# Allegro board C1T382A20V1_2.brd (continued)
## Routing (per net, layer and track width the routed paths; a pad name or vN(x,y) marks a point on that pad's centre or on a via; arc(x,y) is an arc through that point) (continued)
CAN_5V: length 9.8
  TOP w0.5: R68.1 23.06,48.82 23.07,48.83 R31.1 ; v1(23.84,48.02) R31.1 ; R31.1 23.84,49.89 C49.1 22.71,49.92 Q1.3 ; R69.1 27.23,48.95 v1(27.23,49.68)
  BOTTOM w0.5: v1(23.84,48.02) 25.56,48.02 v1(27.23,49.68)
CAN_CANH: length 3
  TOP w0.2: U8.7 21.8,37.39 R29.1
CAN_CANH2: length 3.1
  TOP w0.2: U9.7 28.63,37.23 R36.1
CAN_CANL: length 3
  TOP w0.2: U8.6 20.54,37.38 R30.1
CAN_CANL2: length 3.1
  TOP w0.2: 26.87,36.8 27.37,37.3 27.37,39.68
CANH: length 32
  TOP w0.2: R29.2 22.28,32.76 22.51,32.53 J15.2 23.66,30.31 23.66,22.08 22.23,20.65 D8.2 22.23,18.23 J16.4 J16.3 20.14,6.1 J17.2
CANH2: length 31.7
  TOP w0.2: R36.2 29.07,32.69 29.27,32.49 J19.2 30.42,30.27 30.42,22.12 28.95,20.65 D9.2 28.95,18.12 J20.4 J20.3 30.94,5.73 J21.2
CANL: length 32
  TOP w0.2: R30.2 20.07,32.7 19.9,32.53 J18.2 18.75,30.31 18.75,22.06 20.19,20.61 D8.1 20.19,18.74 J16.6 J16.5 17.61,5.52 J17.1
CANL2: length 31.5
  TOP w0.2: J21.1 28.4,5.88 J20.5 J20.6 26.91,17.62 D9.1 26.91,20.65 25.48,22.08 25.48,30.21 J22.2 26.68,32.49 26.87,32.67 R37.2
DCDC_12V: length 43.8
  TOP w0.5: R53.1 56.02,16.58 C57.1 56.02,17.69 D14.C 58.16,19.82 61.52,19.82 62.21,19.14 C58.1 62.59,19.86 61.29,21.16 v1(59.29,21.16)
  POWER w0.5: S1.6 S1.1 50.25,30.2 v1(59.29,21.16)
DM2: length 53.2
  TOP w0.2: U3.8 36.5,37.55 37.19,36.86 39.79,36.86 v1(39.89,36.96) ; v1(65.03,11.16) 65.03,11 65.04,11 D2.2 65.03,10.45 64.71,10.12 64.71,10.11 64.66,10.07 J8.A7 64.66,6.65 64.42,6.42 63.89,6.42 63.66,6.65 J8.B7
  POWER w0.2: v1(65.03,11.16) 64.19,12 64.19,18.86 46.19,36.86 39.99,36.86 v1(39.89,36.96)
DMICCK: length 51.9
  TOP w0.2: v1(25.69,56.46) 25.69,56.46 23.48,58.67 20.93,58.67 U4.4 19.27,59.5 R9.2 18.33,59.5 12.43,53.6 12.43,49.01 8.96,45.54 J6.13 ; v1(46.38,52.91) 46.9,52.91 U5.4 48.36,53.53 48.38,53.52 R10.2
  BOTTOM w0.2: v1(25.69,56.46) 42.82,56.46 v1(46.38,52.91)
DMICDAT: length 51.8
  TOP w0.2: U5.5 46.7,54.36 36.71,54.36 33.55,57.53 v1(33.55,57.83) ; J6.15 8.96,43 12.96,47 12.96,53.56 17.34,57.94 20.01,57.94 U4.5 20.92,57.03 22.85,57.03 v1(23.59,57.76)
  BOTTOM w0.2: v1(33.55,57.83) 33.48,57.76 v1(23.59,57.76)
DP2: length 53.9
  TOP w0.2: J8.B6 65.16,8.96 65.25,9.05 v1(65.25,9.53) ; v1(39.29,36.26) 37.14,36.26 36,37.4 U3.7 ; v1(63.77,11.2) 63.77,11.03 63.78,11.01 D1.2 64.03,10.18 v1(64.03,9.52) 64.03,9.05 64.16,8.93 J8.A6
  POWER w0.2: v1(63.77,11.2) 63.77,18.71 46.02,36.46 40.29,36.46 40.09,36.26 v1(39.29,36.26)
  BOTTOM w0.2: v1(65.25,9.53) 64.78,9.53 64.78,9.52 v1(64.03,9.52)
EXT_3V3: length 23.7
  POWER w0.5: J9.7 8.78,70.67 8.78,69.01 5.63,65.86 v1(4.73,65.86)
  BOTTOM w0.5: v1(4.73,65.86) 4.73,58.72 7.75,55.7 J29.6 J29.8
EXT_12V: length 126.9
  TOP w0.5: D15.A 82.89,56.22 v1(82.91,56.21) ; 39.02,16.07 37.8,16.07 37.73,16.13 J20.2 ; J31.4 39.11,5.92 39.02,6.01 39.02,13.53
  POWER w0.5: J16.1 J16.2 24.39,17.86 31.75,17.86 J20.2 J20.1 ; 39.02,13.53 39.02,16.07 41.11,18.16 45.25,18.16 47.38,16.02 47.38,13.27 52.8,7.86 69.09,7.86 82.91,21.68 v1(82.91,56.21)
I3C_3V3: length 10.3
  TOP w0.5: R12.2 12.23,2.29 11.47,1.53 6.49,1.53 6.14,1.87 U6.8 6.14,2.72 C37.1 4.75,2.72 R63.2
I3C_ALERT: length 51.5
  TOP w0.2: J6.11 7.86,48.08 6.89,47.11 6.89,36.8 5.43,35.34 5.43,17.84 7.08,16.2 9.63,16.2 12.22,13.61 12.22,4.86 12.23,4.84 R12.1 11.75,3.9 11.64,4.02 U6.3
I3C_SCL: length 11.9
  TOP w0.2: J6.39 8.04,12.52 7.17,11.65 7.17,6.24 10.05,3.37 10.84,3.37
I3C_SDA: length 15.4
  TOP w0.2: 10.84,2.71 10.05,2.71 6.77,5.99 6.77,13.85 7.99,15.06 J6.37
LDO_3V3: length 133.5
  TOP w0.5: v1(50.55,53.29) 50.55,56.45 49.83,57.18 R61.1 ; R66.1 v1(28.02,50.61) ; R64.1 v1(17.84,40.4) ; R70.1 v1(53.38,42.27) ; R67.1 v1(24.67,40.4) ; R65.1 v1(40.91,43.16) ; R63.1 v1(3.84,4.32)
  POWER w0.5: v1(17.84,40.4) v1(24.67,40.4) 28.02,43.75 v1(28.02,50.61) 29.55,50.61 36.99,43.16 v1(40.91,43.16) 50.56,43.16 ; v1(50.55,53.29) 50.55,43.17 50.56,43.16 ; 50.56,43.16 52.49,43.16 v1(53.38,42.27) ; v1(10.29,48.96) 6.59,48.96 v1(5.49,47.86)
  BOTTOM w0.5: v1(17.84,40.4) 17.84,41.42 10.68,48.57 v1(10.29,48.96) ; v1(3.84,4.32) 3.84,10.21 5.49,11.86 v1(5.49,47.86) 5.49,47.96 2.83,50.62 2.1,50.62 2.1,53.16
LDO_5V: length 155.8
  TOP w0.5: v1(87.97,65.46) 87.97,65.47 C63.2 86.93,66.33 C64.1 86.49,66.33 C65.2 84.56,66.33 R57.1 83.62,66.31 83.58,66.28 U14.2 ; v1(6.73,32.84) v1(6.73,25.71)
  BOTTOM w0.5: v1(87.97,65.46) 84.54,65.46 77.63,58.55 77.63,17.7 68.64,8.71 59.69,8.71 57.61,10.79 57.61,14.08 52.8,18.89 8.86,18.89 6.73,21.02 v1(6.73,25.71) ; 8.4,32.84 v1(6.73,32.84)
LDO_VBUS: length 138.9
  TOP w0.5: D18.A 84.89,10.41 84.89,13.06 83.29,14.66 D17.A 83.23,14.65 v1(72.4,14.65) ; v1(20.37,52.99) 20.38,52.98 C48.1 21.53,52.26 Q1.2 21.54,52.93 R33.1
  POWER w0.5: v1(10.59,52.96) 8.09,50.46 5.49,50.46 2.99,47.96 v1(2.99,36.76) ; v1(11.89,26.46) v1(4.69,26.46)
  BOTTOM w0.5: v1(20.37,52.99) 20.34,52.96 v1(10.59,52.96) ; v1(4.69,26.46) 4.69,30.66 2.51,32.84 J29.23 2.1,35.38 2.49,35.38 2.99,35.88 v1(2.99,36.76) ; v1(11.89,26.46) 12.89,26.46 19.59,19.76 53.03,19.76 60.53,12.26 70.01,12.26 v1(72.4,14.65)
LED_B: length 21.5
  TOP w0.2: R17.1 56.35,49.23 58.39,47.2 v1(59.86,47.2) ; v1(68.27,46.23) 68.27,44.97 J7.25
  BOTTOM w0.2: v1(59.86,47.2) 60.83,46.23 v1(68.27,46.23)
LED_G: length 22.2
  TOP w0.2: v1(68.36,40.98) J7.29 ; R19.1 55.83,46.02 57.55,44.3 v1(58.2,44.3)
  BOTTOM w0.2: v1(58.2,44.3) 58.53,43.97 64.51,43.97 67.49,40.98 v1(68.36,40.98)
LED_R: length 20.4
  TOP w0.2: J7.23 67.81,47.42 66.92,48.31 66.92,48.37 v1(66.59,48.7) ; R16.1 56.35,50.85 58.23,48.97 v1(59.92,48.97)
  BOTTOM w0.2: v1(66.59,48.7) 66.32,48.97 v1(59.92,48.97)
LED_W: length 21.8
  TOP w0.2: v1(58.19,45.8) 58.18,45.8 56.35,47.64 R18.1 ; v1(68.41,43.45) 68.41,42.39 J7.27
  BOTTOM w0.2: v1(58.19,45.8) 65.21,45.8 67.57,43.45 v1(68.41,43.45)
LIN1_3V3: length 4.6
  TOP w0.4: R65.2 42.62,42.29 R51.2
  TOP w0.5: v1(45.18,40.94) 45.18,40.4 R39.1 ; R51.2 v1(43.06,42.28)
  BOTTOM w0.5: v1(43.06,42.28) 43.84,42.28 v1(45.18,40.94)
LIN1_12V: length 7.7
  TOP w0.4: D10.A 44.09,25.71 43.27,26.52 43.27,28.57 43.49,28.8 C52.2
  TOP w0.5: R71.2 44.79,28.8 C52.2 43.89,31.23
LIN2_3V3: length 4.5
  TOP w0.4: R70.2 51.16,42.27 51.12,42.3 50.09,42.3 R52.2
  TOP w0.5: R41.1 51.73,41.64 51.72,41.65 R70.2
LIN2_12V: length 7.6
  TOP w0.4: D11.A 50.64,25.6 49.84,26.41 49.84,28.39 50.43,28.99 C56.2 ; C56.2 51.35,28.99 R72.2 ; C56.2 50.45,29.06 50.46,29.07 50.46,30.53
  TOP w0.5: 50.46,31.23 50.46,30.53
LIN_12V: length 51.4
  TOP w0.5: v1(44.79,27.15) 44.79,27.8 R71.1 ; R72.1 v1(51.36,27.26)
  BOTTOM w0.5: v1(51.36,27.26) 51.35,27.26 50.85,26.76 45.18,26.76 v1(44.79,27.15) 44.79,29.16 39.79,34.16 16.49,34.16 10.19,40.46 J29.18
LIN_EN1: length 48
  TOP w0.2: J6.5 8.96,55.7 14.02,60.76 26.82,60.76 43.88,43.7 R43.1
LIN_EN2: length 27.4
  TOP w0.2: R44.1 v1(50.46,40.89) ; v1(68.36,56.36) J7.15
  BOTTOM w0.2: v1(68.36,56.36) 67.45,56.36 66.59,55.51 66.59,54.8 63.26,51.47 59.39,51.47 50.46,42.54 v1(50.46,40.89)
LIN_LIN1: length 32.5
  TOP w0.4: J31.2 44.09,9.72 J25.6 J25.5 40.64,19.52 40.64,24.25 J23.2 40.8,26.58 40.8,28.34 41.02,28.56 41.05,28.56 D12.2 41.46,28.98 42.31,28.98 C55.2 42.62,29.23 42.62,30.48
  TOP w0.5: 42.62,30.48 42.62,31.23
LIN_LIN2: length 32.2
  TOP w0.4: J31.1 52.46,6.43 J27.6 J27.5 47.12,21.37 47.12,24.11 J24.2 47.23,26.63 47.23,28.59 47.7,29.06 47.87,29.06 D13.2 48.45,29.06 48.45,29.06 48.79,29.06 C54.2 49.19,29.46 49.19,30.21
  TOP w0.5: 49.19,31.23 49.19,31.22 49.19,30.21
LIN_RXD1: length 51.9
  TOP w0.2: J6.3 8.97,58.24 11.89,61.16 26.99,61.16 44.52,43.63 44.52,40.04 R39.2 45.17,37.88 45.16,37.88 U10.1
LIN_RXD2: length 29.3
  TOP w0.2: v1(52.54,39.38) R41.2 51.73,39.38 U11.1 ; J7.17 68.36,53.89 v1(68.34,53.87)
  BOTTOM w0.2: v1(52.54,39.38) 52.54,44.05 59.56,51.07 63.42,51.07 66.22,53.86 67.78,53.86 67.78,53.87 v1(68.34,53.87)
LIN_TXD1: length 46.4
  TOP w0.2: R47.1 40.37,42.25 40.37,46.64 26.65,60.36 16.16,60.36 8.96,53.16 J6.7
LIN_TXD2: length 48.4
  TOP w0.2: R49.1 47.23,41.29 46.48,42.04 46.48,42.34 46.41,42.42 46.3,42.42 27.16,61.56 11.49,61.56 10.71,60.78 J6.1
TL_ANT: length 3
  TOP w0.2: 35.49,77.56 35.48,77.54 35.25,77.54 34.99,77.28 U1.43
  TOP w0.5: 35.49,77.56 35.52,77.56 C3.1 L1.1
TL_AVDD1P2: length 11.1
  TOP w0.2: C18.1 34.79,68.29 34.2,68.89 U1.26
  TOP w0.3: 37.89,65.46 39.69,65.46 39.99,65.16 AVDD1P2.1
  TOP w0.35: AVDD1P2.1 R138.2 ; 36.02,66.93 36.42,66.93 37.89,65.46
  TOP w0.4: C18.1 34.79,68.16 36.02,66.93
TL_CAN_RXD: length 29.9
  TOP w0.2: J6.31 8.96,22.68 12.63,26.35 12.63,38 19.27,44.64 U8.4 C43.2
TL_CAN_RXD2: length 33.7
  TOP w0.2: v1(13.67,27.76) 13.43,28.01 13.43,37.5 17.59,41.66 20.93,41.66 23.64,44.37 25.62,44.37 26.09,44.84 U9.4 26.09,47.28 26.08,47.3 C46.2 ; J6.27 v1(11.42,27.76)
  BOTTOM w0.2: v1(11.42,27.76) v1(13.67,27.76)
TL_CAN_STB: length 26.4
  TOP w0.2: R22.2 19.48,36.12 17.88,34.52 17.88,27.09 10.93,20.14 J6.33
TL_CAN_STB2: length 33.8
  TOP w0.2: J6.35 8.96,17.6 18.28,26.92 18.28,33.73 19.38,34.83 29.44,34.83 R24.2
TL_CAN_TXD: length 30.2
  TOP w0.2: v1(12.47,25.22) 13.03,25.78 13.03,37.8 17.29,42.05 20.52,42.05 23.07,44.61 U8.1 ; J6.29 v1(10.56,25.22)
  BOTTOM w0.2: v1(10.56,25.22) 11.96,25.22 11.96,25.22 v1(12.47,25.22)
TL_CAN_TXD2: length 33.3
  TOP w0.2: U9.1 29.91,42.73 28.42,41.25 24.77,41.25 24.61,41.09 24.15,41.09 23.99,41.25 17.78,41.25 13.98,37.45 v1(13.98,30.3) ; v1(11.49,30.3) J6.25
  BOTTOM w0.2: v1(11.49,30.3) 13.51,30.3 13.51,30.3 v1(13.98,30.3)
TL_KEY1: length 29.6
  TOP w0.2: SW4.1 SW4.2 75.28,87.41 74.51,88.18 68.05,88.18 67.28,87.41 SW3.2 SW3.1 67.28,77.31 68.36,76.23 J7.1
TL_KEY2: length 50.4
  TOP w0.2: SW5.2 v1(83.28,81.79) SW5.1 ; SW6.2 v1(59.28,81.79) SW6.1 ; v1(70.11,81.79) 70.11,80.16 70.14,80.12 70.14,74.05 68.91,72.82 J7.3
  BOTTOM w0.2: v1(83.28,81.79) v1(70.11,81.79) v1(59.28,81.79)
TL_KEY3: length 42.8
  TOP w0.2: SW5.3 v1(87.78,83.07) SW5.4 ; SW3.4 v1(71.78,83.07) SW3.3 71.78,73.15 68.91,70.28 J7.5
  BOTTOM w0.2: v1(71.78,83.07) v1(87.78,83.07)
TL_KEY4: length 63.6
  TOP w0.2: 78.61,88.58 64.95,88.58 63.78,87.41 SW6.4 SW6.3 63.78,71.77 67.81,67.74 J7.7 68.91,67.74 79.78,78.61 SW4.3 SW4.4 79.78,87.41 78.61,88.58
TL_MICBIAS: length 27.1
  TOP w0.2: v1(70.22,60.14) 68.38,60.14 J7.13
  TOP w0.5: R4.1 75.03,37.5 v1(75.03,37.5)
  BOTTOM w0.2: v1(70.22,60.14) 70.22,42.31 v1(75.03,37.5)
TL_PA0: length 44.9
  TOP w0.2: U1.16 30.2,69.47 29.39,68.66 28.09,68.66 26.39,66.96 v1(26.39,66.66) ; v1(60.41,65.2) J7.10
  POWER w0.2: v1(26.39,66.66) 28.29,66.66 33.39,61.56 56.77,61.56 v1(60.41,65.2)
TL_PA1: length 43.8
  TOP w0.2: v1(60.41,62.66) J7.12 ; U1.17 30.59,69.27 29.49,68.16 28.39,68.16 26.99,66.76 v1(26.99,66.06)
  POWER w0.2: v1(60.41,62.66) 58.91,61.16 33.09,61.16 28.19,66.06 v1(26.99,66.06)
TL_PA2: length 43.2
  TOP w0.2: v1(27.59,65.46) 27.59,66.56 28.69,67.66 29.69,67.66 30.99,68.96 U1.18 ; v1(60.41,60.12) J7.14
  POWER w0.2: v1(27.59,65.46) 27.69,65.46 32.39,60.76 59.77,60.76 v1(60.41,60.12)
TL_PA7: length 30.8
  TOP w0.2: U1.19 31.39,68.77 28.69,66.06 28.69,65.36 27.59,64.26 23.29,64.26 v1(22.89,64.66) ; R135.2 v1(6.3,68.08)
  BOTTOM w0.2: v1(6.3,68.08) 19.47,68.08 v1(22.89,64.66)
TL_PB0: length 60.8
  TOP w0.2: 18.22,82.29 17.97,82.54 ; 18.22,82.29 17.99,82.06 ; 18.22,82.29 18.45,82.06 ; 17.97,82.54 16.43,84.08 J10.1 ; 17.97,82.54 17.97,82.08 17.99,82.06 ; 17.99,82.06 17.84,81.91 v1(12.79,76.86) ; 17.99,82.06 18.45,82.06 ; 18.45,82.06 31.41,82.06 34.2,79.28 U1.45 ; v1(2.11,62.26) J6.2
  POWER w0.2: v1(2.11,62.26) 2.11,71.78 3.69,73.36 9.29,73.36 v1(12.79,76.86) ; J10.3 J10.1
TL_PB1: length 47.6
  TOP w0.2: U1.46 33.8,79.11 31.26,81.64 20.4,81.64 8.51,69.76 8.51,67.38 3.64,62.5 3.64,59.75 2.14,58.24 J6.4
TL_PB2: length 49.2
  TOP w0.2: U1.47 33.39,78.94 31.09,81.24 20.57,81.24 8.91,69.59 8.91,67.2 4.04,62.33 4.04,57.09 2.66,55.7 J6.6
TL_PB3: length 50.6
  TOP w0.2: J6.8 2.69,53.16 4.44,54.92 4.44,62.17 9.31,67.03 9.31,69.42 20.74,80.84 30.92,80.84 32.99,78.77 U1.48
TL_PB4: length 27.5
  TOP w0.2: U1.29 36.2,70.88 36.59,70.49 36.63,70.49 37.16,69.95 40.8,69.95 41.79,68.96 v1(47.49,68.96) ; J7.8 61.98,67.66 v1(60.39,67.66)
  POWER w0.2: v1(60.39,67.66) 59.09,68.96 v1(47.49,68.96)
TL_PB5: length 27.2
  TOP w0.2: J7.6 60.41,70.28 v1(60.39,70.26) ; v1(46.69,69.56) 41.79,69.56 40.99,70.36 37.32,70.36 36.4,71.28 U1.30
  POWER w0.2: v1(46.69,69.56) 59.69,69.56 v1(60.39,70.26)
TL_PB6: length 27.9
  TOP w0.2: U1.31 36.56,71.68 37.49,70.75 41.3,70.75 41.89,70.16 v1(47.49,70.16) ; v1(60.39,72.86) 62.02,72.86 J7.4
  POWER w0.2: v1(47.49,70.16) 57.69,70.16 v1(60.39,72.86)
TL_PB7: length 28.5
  TOP w0.2: v1(60.49,75.36) J7.2 ; U1.32 36.73,72.08 37.65,71.16 41.69,71.16 41.99,70.86 v1(46.69,70.86)
  POWER w0.2: v1(60.49,75.36) 55.99,70.86 v1(46.69,70.86)
TL_PC0: length 74.5
  TOP w0.2: 62.49,37.26 v1(63.79,37.26) ; 62.49,37.26 J7.32 ; 62.49,37.26 63.39,36.36 63.39,35.46 62.65,34.72 J7.34 ; U1.35 42.36,73.28 42.48,73.16 43.09,73.16 44.84,71.41 v1(47.44,71.41)
  POWER w0.2: v1(63.79,37.26) 64.26,37.73 64.26,73.89 61.89,76.26 58.37,76.26 53.52,71.41 v1(47.44,71.41)
TL_PC1: length 80.4
  TOP w0.2: J7.36 62.57,32.18 ; 62.57,32.18 v1(63.87,32.18) ; 62.57,32.18 63.39,31.36 63.39,30.36 62.67,29.64 J7.38 ; U1.36 42.53,73.68 42.66,73.56 43.39,73.56 44.59,72.36 v1(45.59,72.36)
  POWER w0.2: v1(63.87,32.18) 64.66,32.97 64.66,74.29 62.29,76.66 58.2,76.66 53.5,71.96 45.99,71.96 v1(45.59,72.36)
TL_PC2: length 85.2
  TOP w0.2: 47.02,74.69 47.02,74.59 46.49,74.06 v1(46.49,72.56) ; 47.02,74.69 R2.2 ; 47.02,74.69 46.22,74.69 45.49,73.96 42.82,73.96 42.7,74.08 U1.37 ; J7.40 v1(63.83,27.1)
  POWER w0.2: v1(46.49,72.56) 53.49,72.56 57.99,77.06 62.79,77.06 65.06,74.79 65.06,28.33 v1(63.83,27.1)
TL_PC3: length 86.4
  TOP w0.2: v1(51.29,77.46) 50,76.17 Y1.1 49.28,76.17 48.75,76.7 47.59,76.7 C6.2 46.81,76.19 44.99,74.36 42.99,74.36 42.87,74.48 U1.38 ; J7.42 v1(65.46,24.56)
  POWER w0.2: v1(65.46,24.56) 65.46,75.29 63.29,77.46 v1(51.29,77.46)
TL_PC4: length 64.6
  TOP w0.2: U1.39 43.04,74.88 43.16,74.76 44.59,74.76 v1(47.29,77.46) ; J7.24 63.54,47.42 63.55,47.42 v1(63.71,47.42)
  POWER w0.2: v1(66.01,47.42) 65.9,47.53 65.9,75.65 63.49,78.06 47.89,78.06 v1(47.29,77.46)
  BOTTOM w0.2: v1(66.01,47.42) 65.54,47.42 65.53,47.42 v1(63.71,47.42)
TL_PC5: length 50.8
  TOP w0.2: v1(56.94,42.57) 56.69,42.82 46.47,42.82 32.2,57.1 U1.21 ; J7.26 60.64,44.88 60.61,44.85 v1(59.97,44.85)
  BOTTOM w0.2: v1(59.97,44.85) 57.42,44.85 56.94,44.37 v1(56.94,42.57)
TL_PC6: length 48.4
  TOP w0.2: U1.22 32.59,57.26 46.64,43.22 60.63,43.22 61.51,42.34 J7.28
TL_PC7: length 53.4
  TOP w0.2: U1.23 32.99,57.43 46.8,43.62 63.01,43.62 63.69,42.94 63.69,40.88 62.61,39.8 J7.30
TL_PD0: length 54.2
  TOP w0.2: U1.49 32.59,78.6 30.75,80.44 20.9,80.44 9.71,69.26 9.71,66.86 4.84,62 4.84,52.08 v1(4.49,51.73) ; J6.9 7.93,50.62 7.19,51.36 v1(7.19,51.73)
  POWER w0.2: v1(7.19,51.73) v1(4.49,51.73)
TL_PD4: length 71.1
  TOP w0.2: v1(60.41,57.58) J7.16 ; U1.12 24.71,71.68 22.79,69.76 v1(22.79,69.56)
  POWER w0.2: v1(22.79,69.56) 22.79,68.36 30.79,60.36 57.63,60.36 v1(60.41,57.58)
  BOTTOM w0.2: v1(22.79,69.56) 10.29,69.56 8.97,70.88 6.03,70.88 J9.8
TL_PD5: length 74.2
  TOP w0.2: U1.11 24.21,72.08 22.56,70.43 v1(22.49,70.43) v1(20.79,70.43) ; v1(60.35,55.04) J7.18
  POWER w0.2: v1(60.35,55.04) 55.43,59.96 30.59,59.96 22.19,68.36 22.19,70.13 v1(22.49,70.43)
  BOTTOM w0.2: v1(20.79,70.43) 20.16,71.06 10.69,71.06 8.33,73.42 6.03,73.42 J9.6
TL_PD6: length 78.2
  TOP w0.2: J7.20 v1(60.3,52.5) ; v1(22.05,71.36) 22.05,71.42 23.11,72.48 U1.10
  POWER w0.2: v1(22.05,71.36) 22.05,70.92 21.79,70.66 21.79,68.06 30.29,59.56 53.24,59.56 v1(60.3,52.5)
  BOTTOM w0.2: J9.2 5.97,78.56 14.86,78.56 v1(22.05,71.36)
TL_PD7: length 79
  TOP w0.2: J7.22 61.94,50.08 60.61,50.08 59.8,50.89 59.8,50.9 v1(58.68,52.02) ; v1(21.35,71.06) 21.35,71.52 22.72,72.88 U1.9
  POWER w0.2: v1(58.68,52.02) 51.54,59.16 30.09,59.16 21.35,67.89 v1(21.35,71.06)
  BOTTOM w0.2: v1(21.35,71.06) 16.38,76.03 5.96,76.03 J9.4
TL_PE0: length 72.4
  TOP w0.2: U1.14 28.41,70.88 25.69,68.16 19.99,68.16 18.11,66.28 v1(18.11,65.12) ; v1(3.77,15.06) J6.38
  POWER w0.2: v1(18.11,65.12) 18.11,61.78 16.29,59.96 16.29,26 5.35,15.06 v1(3.77,15.06)
TL_PE2: length 74.1
  TOP w0.2: v1(18.66,65.72) 20.6,67.66 26.29,67.66 27.89,69.26 29.39,69.26 29.8,69.67 U1.15 ; v1(3.68,12.52) 3.54,12.52 3.54,12.52 J6.40
  POWER w0.2: v1(3.68,12.52) 16.69,25.53 16.69,59.66 18.66,61.63 v1(18.66,65.72)
TL_PF4: length 53.4
  TOP w0.2: J6.12 2.61,48.08 5.24,50.72 5.24,61.83 10.12,66.69 10.12,69.09 21.07,80.05 30.58,80.05 32.2,78.43 U1.50
TL_PF5: length 54.8
  TOP w0.2: J6.14 2.66,45.54 3.89,46.77 3.89,48.56 5.64,50.31 5.64,61.66 10.51,66.53 10.51,68.93 21.23,79.64 30.41,79.64 31.8,78.26 U1.51
TL_PF6: length 56.1
  TOP w0.2: J6.16 2.66,43 6.09,46.43 6.09,61.53 10.91,66.36 10.91,68.76 21.4,79.25 30.24,79.25 31.39,78.09 U1.52
TL_PF7: length 57.5
  TOP w0.2: U1.53 30.99,77.92 30.07,78.84 21.56,78.84 11.31,68.6 11.31,66.19 6.49,61.36 6.49,44.29 2.66,40.46 J6.18
TL_PG0: length 60.8
  TOP w0.2: v1(6.23,38.26) 5.9,37.93 2.11,37.93 J6.20 ; v1(11.71,65.72) 11.71,68.43 21.73,78.44 29.9,78.44 30.59,77.75 U1.54
  POWER w0.2: v1(11.71,65.72) 11.71,44.28 6.23,38.8 v1(6.23,38.26)
TL_PG1: length 61.2
  TOP w0.2: v1(6.26,37.45) 4.78,37.45 2.71,35.38 J6.22 ; v1(12.27,65.12) 12.27,68.33 12.46,68.51 12.46,68.6 21.9,78.05 29.7,78.05 30.2,77.55 U1.55
  POWER w0.2: v1(6.26,37.45) 6.78,37.97 6.78,38.45 12.29,43.96 12.29,65.1 v1(12.27,65.12)
TL_PG2: length 51.8
  TOP w0.2: J6.17 9.89,40.46 v1(10.79,41.36) ; v1(12.86,65.72) 12.86,68.43 21.96,77.54 29.54,77.54 29.8,77.28 U1.56
  POWER w0.2: v1(10.79,41.36) 12.69,43.26 12.69,62.46 12.86,62.62 v1(12.86,65.72)
TL_PG7: length 56.7
  TOP w0.2: v1(13.41,65.12) 13.41,68.42 21.08,76.08 U1.1 ; v1(11.69,35.46) 9.07,32.84 J6.23
  POWER w0.2: v1(13.41,65.12) 13.41,62.45 13.09,62.13 13.09,36.86 v1(11.69,35.46)
TL_PH0: length 64.4
  TOP w0.2: v1(14.04,65.75) 14.04,68.47 21.25,75.68 U1.2 ; v1(4.09,32.84) J6.24
  POWER w0.2: v1(4.09,32.84) 4.67,32.26 10.87,32.26 13.49,34.88 13.49,61.96 14.04,62.5 v1(14.04,65.75)
TL_PH2: length 64.8
  TOP w0.2: v1(3.89,30.33) 3.92,30.33 3.92,30.3 J6.26 ; v1(14.62,65.12) 14.62,68.48 21.42,75.28 U1.3
  POWER w0.2: v1(3.89,30.33) 9.51,30.33 13.89,34.71 13.89,61.66 14.62,62.39 v1(14.62,65.12)
TL_PH3: length 66
  TOP w0.2: J6.28 v1(3.93,27.76) ; U1.4 21.61,74.88 15.2,68.47 v1(15.2,65.75)
  POWER w0.2: v1(15.2,65.75) 15.2,62.33 14.29,61.42 14.29,33.88 8.17,27.76 v1(3.93,27.76)
TL_PH4: length 72
  TOP w0.2: v1(3.76,25.22) 3.74,25.22 3.74,25.22 J6.30 ; v1(15.77,65.12) 15.77,68.44 21.81,74.48 U1.5
  POWER w0.2: v1(3.76,25.22) 4.92,24.06 12.09,24.06 14.69,26.66 14.69,61.16 15.77,62.25 v1(15.77,65.12)
TL_PH5: length 71.9
  TOP w0.2: J6.32 3.74,22.68 3.74,22.68 v1(3.76,22.68) ; U1.6 22.01,74.08 16.37,68.44 v1(16.37,65.74)
  POWER w0.2: v1(16.37,65.74) 16.37,62.14 15.09,60.86 15.09,26.5 11.27,22.68 v1(3.76,22.68)
TL_PH6: length 72.8
  TOP w0.2: v1(16.98,65.12) 16.98,68.44 22.21,73.68 U1.7 ; v1(3.73,20.14) J6.34
  POWER w0.2: v1(16.98,65.12) 16.98,62 15.49,60.51 15.49,26.33 9.3,20.14 v1(3.73,20.14)
TL_PH7: length 73.6
  TOP w0.2: v1(17.55,65.77) 17.55,68.42 22.41,73.28 U1.8 ; J6.36 3.59,17.6 3.59,17.6 v1(3.68,17.6)
  POWER w0.2: v1(3.68,17.6) 7.32,17.6 15.89,26.16 15.89,60.26 17.55,61.92 v1(17.55,65.77)
TL_RF: length 4.6
  TOP w0.5: J1.1 D16.2 C5.1 L2.2
TL_RST: length 27.7
  TOP w0.2: SW1.2 SW1.1 50.56,78.96 50.55,78.95 C8.1 49.21,78.95 46.96,81.2 40.01,81.2 38.84,80.04 38.84,78.17 36.76,76.08 U1.42
TL_SDMN0: length 13.4
  TOP w0.2: L6.1 71.07,43.81 69.83,45.05 69.83,48.18 69.19,48.82 67.27,48.82 67.05,49.04 67.05,49.04 66.89,49.19 66.89,51.58 67.81,52.5 J7.19
TL_SDMN1: length 12.6
  TOP w0.2: J7.39 67.81,27.1 66.38,25.67 66.38,23.25 71.11,18.51 L4.1
TL_SDMP0: length 4.8
  TOP w0.2: J7.21 68.91,49.96 70.01,51.06 70.01,51.64 70.16,51.78 71.97,51.78 L7.1
TL_SDMP1: length 4.5
  TOP w0.2: J7.41 68.91,24.56 70.1,25.75 70.36,25.75 71.09,26.48 L5.1
TL_VBAT: length 52.6
  TOP w0.2: U1.28 34.99,69.68 35.24,69.44
  TOP w0.35: 37.13,69.09 36.79,69.44 35.24,69.44
  TOP w0.4: v1(37.49,69.06) 37.16,69.06 37.13,69.09
  TOP w0.5: v1(37.49,69.06) 38.41,69.06 C15.1
  POWER w0.5: v1(2.1,59.56) 15.2,72.66 22.99,72.66 24.09,71.56 24.09,69.56 24.59,69.06 v1(37.49,69.06)
  BOTTOM w0.5: 2.1,55.7 v1(2.1,59.56) 2.1,60.78
TL_VDD1P2: length 5.7
  TOP w0.5: VDD1P2.1 R139.1 R138.1 C72.1 37.19,64.76 35.86,63.43 L3.2
TL_VDD3DCDC: length 10.8
  TOP w0.2: U1.24 33.39,68.27 33.47,68.2
  TOP w0.35: 33.69,64.66 33.71,64.66 34.29,65.24 34.29,66.26 33.59,66.96 C17.1 33.47,67.03 33.47,68.2
  TOP w0.4: VDD3DCDC.1 34.29,60.46 34.29,64.06 33.69,64.66 R141.2
TL_VDDCORE: length 4.7
  TOP w0.2: U1.20 31.8,68.36 31.59,68.16
  TOP w0.4: C16.1 31.59,67 31.59,68.16
  TOP w0.5: VDDCORE.1 30.79,66.96 C16.1
TL_VDDIOPE: length 6.1
  TOP w0.2: U1.13 28.11,71.28 27.83,71
  TOP w0.35: C13.1 27.83,71
  TOP w0.4: C13.1 26.59,70.97 R140.2 26.59,70.04 25.81,69.26 VDDIOPE.1
TL_VDDO3: length 71.4
  TOP w0.2: 37.18,72.37 37.07,72.48 U1.33 ; VDDO3.1 42.79,71.56 38.49,71.56 v1(38.31,71.74)
  TOP w0.4: R141.1 v1(33.59,62.96) ; R140.1 v1(24.89,70.06) ; R20.2 v1(22.82,87.61) ; 37.18,72.37 37.34,72.2 C12.1 v1(38.31,71.74)
  POWER w0.4: 26.98,72.16 26.29,71.46 v1(24.89,70.06) ; 26.98,72.16 22.31,76.83 22.31,79.02 ; 26.98,72.16 27.98,71.16 37.73,71.16 v1(38.31,71.74) 38.99,71.06 38.99,66.36 35.59,62.96 v1(33.59,62.96) ; 22.31,79.02 21.78,79.55 21.78,79.57 ; 22.31,79.02 22.31,79.53 ; 22.31,79.53 22.31,80.1 ; 22.31,79.53 22.27,79.57 21.78,79.57 ; 22.31,80.1 22.31,85.88 22.3,85.89 22.3,86.43 22.31,86.44 22.31,87.09 v1(22.82,87.61) ; 22.31,80.1 22.26,80.05 22.09,80.05 21.79,79.75 21.79,79.58 21.78,79.57 ; 21.78,79.57 7.5,79.57 J9.1
TL_VLINE: length 35.8
  TOP w0.2: U1.44 34.59,77.67 34.7,77.77
  TOP w0.4: 34.7,77.77 34.7,79.91 C1.1
  TOP w0.5: VLINE.1 31.19,83.13 v1(32.23,82.09) 32.79,81.53 C2.1 33.07,81.44 33.82,80.69 C1.1 ; R139.2 v1(39.29,62.96)
  BOTTOM w0.4: v1(32.23,82.09) 29.19,79.05 29.19,68.76 34.99,62.96 v1(39.29,62.96)
TL_XC1: length 8.9
  TOP w0.2: 43.43,76.58 43.43,76.62 42.52,77.55 40.74,77.55 40.6,77.4 C11.1 39.22,77.4 37.1,75.28 U1.40
TL_XC2: length 7
  TOP w0.2: Y2.1 40.7,78.31 C9.2 39.55,78.31 36.92,75.68 U1.41
UART_5V: length 15.5
  TOP w0.35: v1(38.66,39.22) R62.1 C75.1 37.28,41.24 U3.9 ; C77.1 31.71,42.5 v1(32.05,42.17) 32.37,41.84 34.33,41.84
  BOTTOM w0.35: v1(32.05,42.17) 34.37,39.85 38.02,39.85 v1(38.66,39.22)
UART_RX: length 48.4
  TOP w0.2: J6.21 8.96,35.38 10.67,37.09 10.67,39.07 15.4,43.8 15.4,49.43 19.96,53.99 28.06,53.99 30.78,51.27 30.78,40.98 R136.2
UART_TX: length 45.9
  TOP w0.2: J6.19 8.96,37.92 15,43.96 15,49.6 19.8,54.39 27.89,54.39 27.89,54.39 28.23,54.39 28.23,54.39 28.29,54.39 31.19,51.49 31.19,41.54 R137.2
USB_5V: length 90
  TOP w0.5: R62.2 v1(38.19,37.71) ; v1(67.29,14.06) 64.09,14.06 60.43,10.4 R15.1
  POWER w0.5: v1(37.89,33.36) 37.89,37.41 v1(38.19,37.71) 38.73,38.26 49.99,38.26 67.29,20.96 v1(67.29,14.06)
  BOTTOM w0.5: J29.20 J29.22 10.27,35.38 12.31,33.34 37.87,33.34 v1(37.89,33.36)
USB_VBUSU: length 10.6
  TOP w0.5: J8.B4A9 66.81,6.59 65.88,5.66 62.94,5.66 62.01,6.59 J8.A4B9 62.01,8.4 D3.2 61.33,8.62 C71.1 60.29,8.62 R15.2
N20253886: length 2.5
  TOP w0.2: U2.4 74.44,39.66 74.48,39.66 R4.2 75.93,39.12 C22.1
N20253935: length 1.2
  TOP w0.2: C21.1 72.17,39.8 72.19,39.78 U2.1
N20253959: length 3.8
  TOP w0.2: C26.1 78.48,39.52 80.33,39.52
N20337202: length 4.4
  TOP w0.2: C23.1 74.41,22.13 R3.1 ; C23.1 C19.2 ; C23.1 73.84,21.56 L4.2
N20337204: length 10.1
  TOP w0.2: J2.2 82.43,18.1 78.41,22.12 C20.2 77.16,22.13 R3.2
N20337251: length 4.3
  TOP w0.2: C23.2 75.22,23.07 R5.1 ; C23.2 74,23.43 L5.2 ; C23.2 C24.1
N20337259: length 6.6
  TOP w0.2: 80.33,26.8 80.33,25.08 78.29,23.04 C25.1 R5.2
N20337346: length 4.4
  TOP w0.2: C31.1 73.78,46.86 L6.2 ; C31.1 74.34,47.42 R7.1 ; C31.1 74.32,46.92 74.32,46.91 C27.2
N20337363: length 10
  TOP w0.2: J4.2 81.32,43.77 77.66,47.42 C28.2 77.15,47.42 R7.2
N20337410: length 4.3
  TOP w0.2: C31.2 74.37,48.34 R8.1 ; C31.2 74.01,48.7 L7.2 ; C31.2 74.32,49.29 C32.1
N20337418: length 6.8
  TOP w0.2: R8.2 76.26,48.35 C33.1 77.97,48.35 80.36,50.75 J4.3
N20392329: length 1.3
  TOP w0.2: R16.2 47.93,50.85 47.93,50.84 D4.A
N20392898: length 1.3
  TOP w0.2: R17.2 47.93,49.23 47.93,49.23 D5.A
N20393445: length 1.3
  TOP w0.2: R18.2 47.95,47.64 47.95,47.63 D6.A
N20393873: length 1.3
  TOP w0.2: D7.A 47.97,46.02 47.97,46.02 R19.2
N20432643: length 1.8
  TOP w0.5: L2.1 C4.1 L1.2
N20432803: length 2.6
  TOP w0.2: R2.1 47.98,73.69 C7.2 49.64,73.72 Y1.2
N20433121: length 5.2
  TOP w0.2: C10.1 40.67,72.88 U1.34
N20433225: length 5.3
  TOP w0.2: 34.02,68.32 33.8,68.54 U1.25
  TOP w0.35: L3.1 35.67,66.34 34.02,68 34.02,68.32
N20446669: length 4.6
  TOP w0.5: D14.A 59.69,18.27 59.08,17.67 U13.1 59.49,15.95 L8.1
N20446778: length 8.5
  TOP w0.5: D17.C 83.24,10.76 81.2,10.76 C59.2 81.15,10.77 C60.1 U12.1 77.87,10.77 77.29,11.35 77.29,12.16 77.8,12.67 U12.3
N20446804: length 3.4
  TOP w0.5: U13.3 57.18,16.11 56.66,15.59 C57.2 56.02,15.58 R53.2 55.11,14.69 R55.1
N20446808: length 2.1
  TOP w0.5: R56.1 57.28,12.84 R54.2 57.18,12.95 U13.4
N20447279: length 4
  TOP w0.5: R57.2 84.55,68.2 R59.1 ; R57.2 85.45,67.31 C65.1 ; R57.2 83.93,67.31 83.69,67.55 U14.3
N20447283: length 3.7
  TOP w0.5: R60.1 74.75,68.73 R58.2 75.38,68.74 76.56,67.55 U14.6
N20449113: length 1.3
  TOP w0.2: R13.2 63.16,8.61 J8.A5
N20449208: length 1.3
  TOP w0.2: J8.B5 66.16,8.62 R14.2
N20451817: length 2.6
  TOP w0.2: R28.1 22.73,27.13 22.51,27.35 J15.1
N20451819: length 3.6
  TOP w0.2: R28.2 21.78,24.41 C47.1 20.63,24.42 R32.2
N20451956: length 2.6
  TOP w0.2: R32.1 19.63,27.14 19.9,27.41 J18.1
N20451988: length 2.6
  TOP w0.2: J19.1 29.27,27.36 29.55,27.08 R35.1
N20451990: length 3.7
  TOP w0.2: R38.2 27.37,24.36 C50.1 28.51,24.36 R35.2
N20452190: length 2.7
  TOP w0.2: R38.1 26.35,27.47 26.68,27.81 J22.1
N20458083: length 2.9
  TOP w0.2: U8.8 23.07,37.88 R22.1
N20458950: length 5.3
  TOP w0.5: R33.2 23.57,52.98 Q1.1 23.57,51.28 23.93,50.92 25.25,50.92 25.88,50.28 Q2.3
N20458968: length 2
  TOP w0.2: Q2.1 27.54,52.24 27.55,52.24 R66.2 28.02,52.25 R34.1
N20459724: length 2.6
  TOP w0.4: R40.2 45.71,29.23 45.16,29.77 45.16,30.48
  TOP w0.5: 45.16,30.48 45.16,31.23
N20459777: length 2.7
  TOP w0.2: U10.3 42.62,37.88 42.64,37.89 R45.2
N20459821: length 2.8
  TOP w0.2: R46.2 49.18,38.11 49.19,38.11 U11.3
N20459876: length 3.6
  TOP w0.2: R47.2 41.35,39.38 C51.2 41.37,37.64 41.35,37.62 U10.4
N20459892: length 1.3
  TOP w0.4: R48.2 44.53,22.21 D10.C
N20459907: length 3.7
  TOP w0.2: R49.2 47.91,39.4 C53.2 U11.4
N20481050: length 8.3
  TOP w0.5: D18.C 83.2,5 81.11,5 81.09,5.01 C70.1 79.83,5.02 U15.1 77.89,5.02 77.41,5.49 77.41,6.44 77.89,6.92 78.45,6.92
N20505812: length 8.9
  TOP w0.2: C73.1 81.69,33.86 J3.2
N20509362: length 5.6
  TOP w0.2: U3.12 37.38,42.84 37.67,43.14 37.67,46.76 37.67,46.76 TP4.1
N20509364: length 4.7
  TOP w0.2: TP5.1 38.62,43.25 37.72,42.34 U3.11
N20509368: length 1.8
  TOP w0.2: U3.10 38.24,41.84 38.25,41.85 TP6.1
N20509433: length 2.6
  TOP w0.2: U3.13 36.5,44.36 36.49,44.37 36.49,46.09 TP8.1
N20509448: length 4.7
  TOP w0.2: TP7.1 35.55,44.53 36,44.09 U3.14
N20509463: length 3.1
  TOP w0.2: U3.15 35.5,44.02 34.45,45.08 TP9.1
N20509471: length 5.3
  TOP w0.2: U3.16 35,43.72 33.42,45.3 33.42,47.39 33.43,47.4 TP10.1
N20509473: length 2.2
  TOP w0.2: U3.5 35,40.47 34.76,40.23 34.52,40.23 R136.1
N20509515: length 1.9
  TOP w0.2: 34.33,41.34 33.13,41.34 32.99,41.2 R137.1
N202577100: length 2.1
  TOP w0.2: J10.2 21.81,84.08 21.81,84.08 R21.1
N202577180: length 2.1
  TOP w0.2: R20.1 21.83,86.61 21.82,86.62 J10.4
N204580687: length 3
  TOP w0.2: U9.8 29.91,38.23 30.63,37.5 R24.1
N204596791: length 2.5
  TOP w0.4: 51.73,30.53 51.73,29.63 51.76,29.63 52.27,29.13 R42.2
  TOP w0.5: 51.73,30.53 51.73,31.23
N204596931: length 2.8
  TOP w0.2: U10.2 43.89,37.62 43.88,37.63 R43.2
N204597071: length 2.8
  TOP w0.2: R44.2 U11.2
N204597510: length 0.9
  TOP w0.2: R45.1 42.64,41.27 R51.1
N204597660: length 0.9
  TOP w0.2: R46.1 49.18,40.4 R52.1
N204598021: length 3.2
  TOP w0.4: J23.1 41.89,21.79 42.79,20.89 R48.1
N204598461: length 3.2
  TOP w0.4: R50.1 49.33,20.82 48.43,21.71 J24.1
N204598551: length 1.3
  TOP w0.4: D11.C 51.09,20.82 R50.2
N205078799: length 2.2
  TOP w0.2: R135.1 J9.9

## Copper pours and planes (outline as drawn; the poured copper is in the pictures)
GND on TOP: 3,0.3 1.09,1.09 0.3,3 0.3,87 1.09,88.91 3,89.7 34.79,89.7 34.79,85.66 35.59,85.66 35.69,85.56 35.69,78.46 35.59,78.36 36.89,78.36 36.89,85.56 36.99,85.66 37.89,85.66 37.89,89.7 87,89.7 88.91,88.91 89.7,87 89.7,3 88.91,1.09 87,0.3 ; 56 cut-outs
GND on BOTTOM: 3,0.3 1.09,1.09 0.3,3 0.3,87 1.09,88.91 3,89.7 34.77,89.7 34.77,85.66 37.85,85.66 37.85,89.7 87,89.7 88.91,88.91 89.7,87 89.7,3 88.91,1.09 87,0.3 ; 12 cut-outs
GND on GND: 0.3,87 1.09,88.91 3,89.7 87,89.7 88.91,88.91 89.7,87 89.7,3 88.91,1.09 87,0.3 3,0.3 1.09,1.09 0.3,3 ; 7 cut-outs
GND on POWER: 3,0.3 1.09,1.09 0.3,3 0.3,87 1.09,88.91 3,89.7 87,89.7 88.91,88.91 89.7,87 89.7,3 88.91,1.09 87,0.3 ; 9 cut-outs

Small or netless copper shapes (teardrops, artwork), in the pictures only: 9 on TOP

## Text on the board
Ref Des/Silkscreen Bottom: CAN1L | CAN1H | CAN2L | CAN2H | EXT_12V | GND | LIN1 | LIN2 | VBAT | VCC_12V | LDO_3V3 | LDO_VBUS | VBUS_DCDC | NC | LIN12V | LDO_5V | USB_5V | EXT_3V3 | VCC_3V3 | VBAT_3V3 | 2026-03-06 | TL3225B_EVK56D | C1T382A20_V1.2
User.Comments: #4 | #3 | #1 | #2 | TOP | #5 | BOTTOM
Ref Des/Silkscreen Top: PE0 | PE2 | TDO | TCK | TMS | TDI | NC | SDA | SCL | VDDO3 | 3V3 | GND | SWS | PB0 | PB1 | PB2 | PF7 | PG0 | PG1 | PH0 | PH7 | PB3 | PF4 | PF5 | PF6 | PH2 | PH4 | PH5 | PH6 | PH3 | LIN1_EN | PD0 | PG7 | CAN2_TX | CAN1_RX | CAN1_STB | CAN2_STB | LIN2_TX | LIN1_TX | DMICCK | CAN2_RX | LIN1_RX | PG2 | TX | RX | DMICDAT | ALERT | CAN1_TX | RI | CTS | DSR | RTS | DTR | DCD | ACT | PB7 | PB6 | PB5 | PB4 | PA0 | PA1 | PA2 | PD4 | PD5 | PC0 | PC5 | PD7 | PD6 | PC4 | PC7 | PC6 | PC1 | PC2 | PC3 | LINEIN_N | LINEIN_P | LIN2_EN | LIN2_RX | MBIAS | AMIC_P | SDMN0 | SDMP0 | AMIC_N | KEY4 | KEY3 | KEY2 | SDMP1 | LEDB | SDMN1 | KEY1 | LEDR | LEDW | LEDG | EXT12V | DC12V | 12V | RST
DISPLAY_TOP: FIGURE | FINISHED_SIZE | 0.3 | 0.7 | 0.889 | 0.9 | 1.2 | 1.0 | DRILL CHART: TOP to BOTTOM | ALL UNITS ARE IN MILLIMETERS | PLATED | NON-PLATED | QTY | 1233 | 4 | 1 | 17 | 5 | 33 | 8 | 2 | 6
